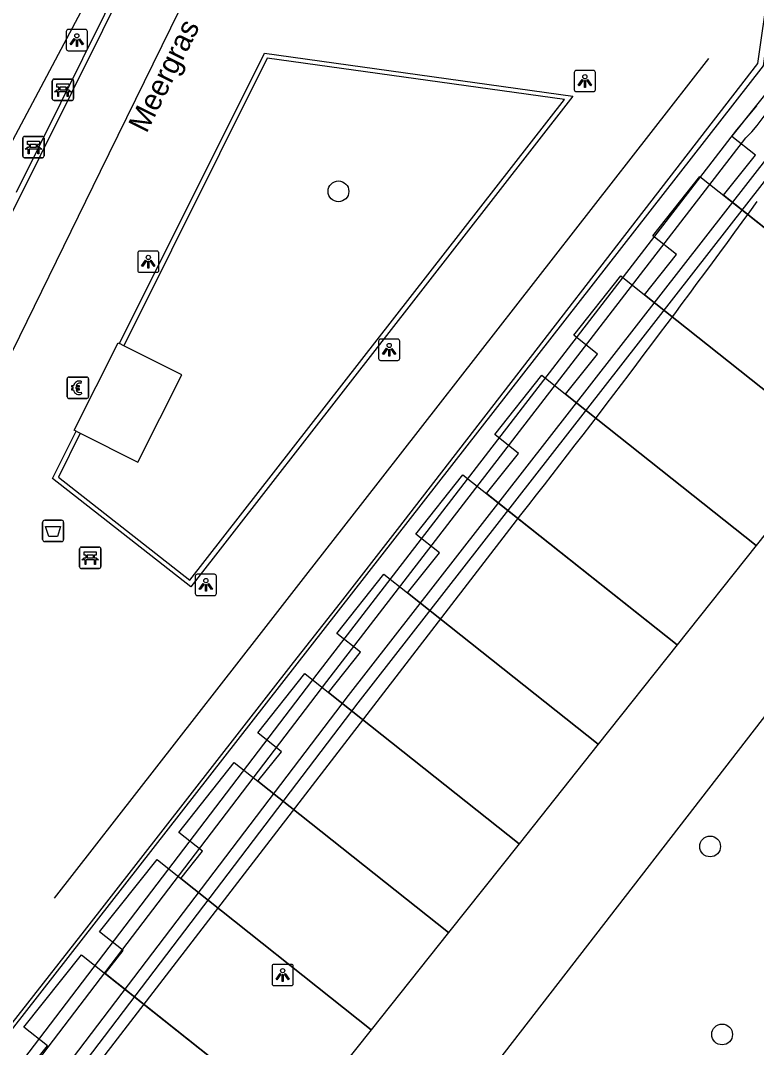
# Model space of a CAD drawing. Extents: x 155640 to 156810, y 382822 to 384046.
# Drawn here: x 156515.13 to 156549.69, y 383555.74 to 383603.99 of the extents above; entities that cross this region are included whole.
import ezdxf

# ---------------------------------------------------------------- set-up
doc = ezdxf.new("R2010")
doc.units = 0
for name, color, linetype in [('IMGEO_Afvalbak', 7, 'Continuous'), ('IMGEO_Bank', 7, 'Continuous'), ('IMGEO_Betaalautomaat', 7, 'Continuous'), ('IMGEO_Boom', 7, 'Continuous'), ('IMGEO_Groenvoorziening', 7, 'Continuous'), ('IMGEO_Lichtpunt', 7, 'Continuous'), ('IMGEO_Lijnafwatering', 7, 'Continuous'), ('IMGEO_Muur', 7, 'Continuous'), ('IMGEO_Openbare_ruimte_label', 7, 'Continuous'), ('IMGEO_Pand_vergunning_verleend', 7, 'Continuous'), ('IMGEO_Rijbaan_lokaal_gesloten', 7, 'Continuous'), ('IMGEO_Voetgangersgebied_gesloten', 7, 'Continuous'), ('IMGEO_Waterloop', 7, 'Continuous')]:
    doc.layers.add(name, color=color, linetype=linetype)

msp = doc.modelspace()

# ---------------------------------------------------------------- linework, layer by layer
at = {"layer": 'IMGEO_Afvalbak'}
for p, q in [((156516.16, 383579.606), (156516.16, 383580.406)), ((156516.16, 383580.406), (156516.16, 383579.606)), ((156516.26, 383580.506), (156517.05, 383580.506)), ((156517.05, 383580.506), (156516.26, 383580.506)), ((156517.15, 383580.406), (156517.15, 383579.606)), ((156517.15, 383579.606), (156517.15, 383580.406)), ((156517.05, 383579.506), (156516.26, 383579.506)), ((156516.26, 383579.506), (156517.05, 383579.506))]:
    msp.add_line(p, q, dxfattribs=at)
msp.add_lwpolyline([(156516.303, 383580.22), (156517.007, 383580.22), (156516.858, 383579.75), (156516.452, 383579.75), (156516.303, 383580.22)], dxfattribs=at)
for centre, start, end in [((156516.26, 383580.406), 90, 180), ((156516.26, 383580.406), 90, 180), ((156517.05, 383580.406), 0, 90), ((156517.05, 383580.406), 360, 90), ((156516.26, 383579.606), 180, 270), ((156516.26, 383579.606), 180, 270), ((156517.05, 383579.606), 270, 0), ((156517.05, 383579.606), 270, 0)]:
    msp.add_arc(centre, 0.1, start, end, dxfattribs=at)
at = {"layer": 'IMGEO_Bank'}
for p, q in [((156516.618, 383600.309), (156516.618, 383601.15)), ((156516.618, 383601.15), (156516.618, 383600.309)), ((156516.693, 383601.234), (156517.534, 383601.234)), ((156517.534, 383601.234), (156516.693, 383601.234)), ((156517.618, 383601.159), (156517.618, 383600.318)), ((156517.618, 383600.318), (156517.618, 383601.159)), ((156517.315, 383600.632), (156516.922, 383600.632)), ((156516.927, 383600.74), (156516.927, 383600.846)), ((156516.971, 383600.846), (156516.971, 383600.74)), ((156517.259, 383600.852), (156516.977, 383600.852)), ((156516.977, 383600.734), (156517.259, 383600.734)), ((156517.265, 383600.74), (156517.265, 383600.846)), ((156517.309, 383600.846), (156517.309, 383600.74)), ((156517.543, 383600.234), (156516.702, 383600.234)), ((156516.702, 383600.234), (156517.543, 383600.234)), ((156515.23, 383597.615), (156515.23, 383598.456)), ((156515.23, 383598.456), (156515.23, 383597.615)), ((156515.305, 383598.54), (156516.146, 383598.54)), ((156516.146, 383598.54), (156515.305, 383598.54)), ((156515.539, 383598.046), (156515.539, 383598.152)), ((156515.583, 383598.152), (156515.583, 383598.046)), ((156515.871, 383598.158), (156515.589, 383598.158)), ((156515.877, 383598.046), (156515.877, 383598.152)), ((156515.921, 383598.152), (156515.921, 383598.046)), ((156516.23, 383598.465), (156516.23, 383597.624)), ((156516.23, 383597.624), (156516.23, 383598.465)), ((156515.927, 383597.938), (156515.534, 383597.938)), ((156515.589, 383598.04), (156515.871, 383598.04)), ((156516.155, 383597.54), (156515.314, 383597.54)), ((156515.314, 383597.54), (156516.155, 383597.54)), ((156517.899, 383578.32), (156517.899, 383579.161)), ((156517.899, 383579.161), (156517.899, 383578.32)), ((156517.974, 383579.245), (156518.815, 383579.245)), ((156518.815, 383579.245), (156517.974, 383579.245)), ((156518.208, 383578.751), (156518.208, 383578.857)), ((156518.252, 383578.857), (156518.252, 383578.751)), ((156518.54, 383578.863), (156518.258, 383578.863)), ((156518.546, 383578.751), (156518.546, 383578.857)), ((156518.59, 383578.857), (156518.59, 383578.751)), ((156518.899, 383579.17), (156518.899, 383578.329)), ((156518.899, 383578.329), (156518.899, 383579.17)), ((156518.596, 383578.643), (156518.203, 383578.643)), ((156518.258, 383578.745), (156518.54, 383578.745)), ((156518.824, 383578.245), (156517.983, 383578.245)), ((156517.983, 383578.245), (156518.824, 383578.245))]:
    msp.add_line(p, q, dxfattribs=at)
for points in [[(156516.865, 383600.632), (156516.723, 383600.632), (156516.835, 383600.734), (156516.921, 383600.734)], [(156516.921, 383600.852), (156516.835, 383600.852), (156516.835, 383601.013), (156517.398, 383601.013), (156517.398, 383600.852), (156517.315, 383600.852)], [(156516.915, 383600.625), (156516.915, 383600.418), (156516.872, 383600.418), (156516.872, 383600.625)], [(156517.315, 383600.734), (156517.398, 383600.734), (156517.51, 383600.632), (156517.371, 383600.632)], [(156517.365, 383600.625), (156517.365, 383600.418), (156517.321, 383600.418), (156517.321, 383600.625)], [(156515.533, 383598.158), (156515.447, 383598.158), (156515.447, 383598.319), (156516.01, 383598.319), (156516.01, 383598.158), (156515.927, 383598.158)], [(156515.477, 383597.938), (156515.335, 383597.938), (156515.447, 383598.04), (156515.533, 383598.04)], [(156515.527, 383597.931), (156515.527, 383597.724), (156515.484, 383597.724), (156515.484, 383597.931)], [(156515.927, 383598.04), (156516.01, 383598.04), (156516.122, 383597.938), (156515.983, 383597.938)], [(156515.977, 383597.931), (156515.977, 383597.724), (156515.933, 383597.724), (156515.933, 383597.931)], [(156518.202, 383578.863), (156518.116, 383578.863), (156518.116, 383579.024), (156518.679, 383579.024), (156518.679, 383578.863), (156518.596, 383578.863)], [(156518.146, 383578.643), (156518.004, 383578.643), (156518.116, 383578.745), (156518.202, 383578.745)], [(156518.196, 383578.636), (156518.196, 383578.429), (156518.153, 383578.429), (156518.153, 383578.636)], [(156518.596, 383578.745), (156518.679, 383578.745), (156518.791, 383578.643), (156518.652, 383578.643)], [(156518.646, 383578.636), (156518.646, 383578.429), (156518.602, 383578.429), (156518.602, 383578.636)]]:
    msp.add_lwpolyline(points, dxfattribs=at)
for centre, radius, start, end in [((156516.696, 383601.156), 0.0779, 92.4484, 184.2845), ((156516.696, 383601.156), 0.0779, 92.4484, 184.2845), ((156517.54, 383601.156), 0.0779, 2.4484, 94.2845), ((156517.54, 383601.156), 0.0779, 2.4484, 94.2845), ((156516.865, 383600.625), 0.00671, 2.8957, 87.1043), ((156516.922, 383600.625), 0.00671, 92.8957, 177.1043), ((156516.92, 383600.845), 0.00671, 2.8957, 87.1043), ((156516.92, 383600.741), 0.00671, 272.8957, 357.1043), ((156516.977, 383600.845), 0.00671, 92.8957, 177.1043), ((156516.977, 383600.741), 0.00671, 182.8957, 267.1043), ((156517.259, 383600.845), 0.00671, 2.8957, 87.1043), ((156517.259, 383600.741), 0.00671, 272.8957, 357.1043), ((156517.316, 383600.845), 0.00671, 92.8957, 177.1043), ((156517.316, 383600.741), 0.00671, 182.8957, 267.1043), ((156517.314, 383600.625), 0.00671, 2.8957, 87.1043), ((156517.371, 383600.625), 0.00671, 92.8957, 177.1043), ((156516.696, 383600.312), 0.0779, 182.4484, 274.2845), ((156516.696, 383600.312), 0.0779, 182.4484, 274.2845), ((156517.54, 383600.312), 0.0779, 272.4484, 4.2845), ((156517.54, 383600.312), 0.0779, 272.4484, 4.2845), ((156515.308, 383598.462), 0.0779, 92.4484, 184.2845), ((156515.308, 383598.462), 0.0779, 92.4484, 184.2845), ((156515.532, 383598.151), 0.00671, 2.8957, 87.1043), ((156515.589, 383598.151), 0.00671, 92.8957, 177.1043), ((156515.871, 383598.151), 0.00671, 2.8957, 87.1043), ((156515.928, 383598.151), 0.00671, 92.8957, 177.1043), ((156516.152, 383598.462), 0.0779, 2.4484, 94.2845), ((156516.152, 383598.462), 0.0779, 2.4484, 94.2845), ((156515.477, 383597.931), 0.00671, 2.8957, 87.1043), ((156515.534, 383597.931), 0.00671, 92.8957, 177.1043), ((156515.532, 383598.047), 0.00671, 272.8957, 357.1043), ((156515.589, 383598.047), 0.00671, 182.8957, 267.1043), ((156515.871, 383598.047), 0.00671, 272.8957, 357.1043), ((156515.928, 383598.047), 0.00671, 182.8957, 267.1043), ((156515.926, 383597.931), 0.00671, 2.8957, 87.1043), ((156515.983, 383597.931), 0.00671, 92.8957, 177.1043), ((156515.308, 383597.618), 0.0779, 182.4484, 274.2845), ((156515.308, 383597.618), 0.0779, 182.4484, 274.2845), ((156516.152, 383597.618), 0.0779, 272.4484, 4.2845), ((156516.152, 383597.618), 0.0779, 272.4484, 4.2845), ((156517.977, 383579.167), 0.0779, 92.4484, 184.2845), ((156517.977, 383579.167), 0.0779, 92.4484, 184.2845), ((156518.201, 383578.856), 0.00671, 2.8957, 87.1043), ((156518.258, 383578.856), 0.00671, 92.8957, 177.1043), ((156518.54, 383578.856), 0.00671, 2.8957, 87.1043), ((156518.597, 383578.856), 0.00671, 92.8957, 177.1043), ((156518.821, 383579.167), 0.0779, 2.4484, 94.2845), ((156518.821, 383579.167), 0.0779, 2.4484, 94.2845), ((156518.146, 383578.636), 0.00671, 2.8957, 87.1043), ((156518.203, 383578.636), 0.00671, 92.8957, 177.1043), ((156518.201, 383578.752), 0.00671, 272.8957, 357.1043), ((156518.258, 383578.752), 0.00671, 182.8957, 267.1043), ((156518.54, 383578.752), 0.00671, 272.8957, 357.1043), ((156518.597, 383578.752), 0.00671, 182.8957, 267.1043), ((156518.595, 383578.636), 0.00671, 2.8957, 87.1043), ((156518.652, 383578.636), 0.00671, 92.8957, 177.1043), ((156517.977, 383578.323), 0.0779, 182.4484, 274.2845), ((156517.977, 383578.323), 0.0779, 182.4484, 274.2845), ((156518.821, 383578.323), 0.0779, 272.4484, 4.2845), ((156518.821, 383578.323), 0.0779, 272.4484, 4.2845)]:
    msp.add_arc(centre, radius, start, end, dxfattribs=at)
at = {"layer": 'IMGEO_Betaalautomaat'}
for p, q in [((156517.317, 383586.307), (156517.317, 383587.148)), ((156517.317, 383587.148), (156517.317, 383586.307)), ((156517.392, 383587.231), (156518.233, 383587.231)), ((156518.233, 383587.231), (156517.392, 383587.231)), ((156517.979, 383587.036), (156517.962, 383586.936)), ((156518.316, 383587.157), (156518.316, 383586.316)), ((156518.316, 383586.316), (156518.316, 383587.157)), ((156517.6, 383586.695), (156517.6, 383586.763)), ((156517.721, 383586.763), (156517.721, 383586.695)), ((156518.242, 383586.232), (156517.401, 383586.232)), ((156517.401, 383586.232), (156518.242, 383586.232)), ((156517.966, 383586.53), (156517.988, 383586.443))]:
    msp.add_line(p, q, dxfattribs=at)
for points in [[(156517.6, 383586.763), (156517.531, 383586.763), (156517.531, 383586.832), (156517.61, 383586.832)], [(156517.605, 383586.626), (156517.531, 383586.626), (156517.531, 383586.695), (156517.6, 383586.695)], [(156517.732, 383586.832), (156517.879, 383586.832), (156517.879, 383586.763), (156517.721, 383586.763)], [(156517.721, 383586.695), (156517.879, 383586.695), (156517.879, 383586.626), (156517.735, 383586.626)]]:
    msp.add_lwpolyline(points, dxfattribs=at)
for centre, radius, start, end in [((156517.395, 383587.154), 0.0779, 92.4484, 184.2845), ((156517.395, 383587.154), 0.0779, 92.4484, 184.2845), ((156517.893, 383586.756), 0.293, 73.014, 165.0139), ((156518.239, 383587.154), 0.0779, 2.4484, 94.2845), ((156518.239, 383587.154), 0.0779, 2.4484, 94.2845), ((156517.866, 383586.681), 0.267, 191.8096, 297.0389), ((156517.899, 383586.769), 0.179, 69.3236, 159.5683), ((156517.899, 383586.696), 0.179, 202.7625, 291.8693), ((156517.395, 383586.31), 0.0779, 182.4484, 274.2845), ((156517.395, 383586.31), 0.0779, 182.4484, 274.2845), ((156518.239, 383586.31), 0.0779, 272.4484, 4.2845), ((156518.239, 383586.31), 0.0779, 272.4484, 4.2845)]:
    msp.add_arc(centre, radius, start, end, dxfattribs=at)
at = {"layer": 'IMGEO_Boom'}
for centre in [(156530.057, 383595.961), (156547.515, 383565.182), (156548.078, 383556.351)]:
    msp.add_circle(centre, 0.489, dxfattribs=at)
at = {"layer": 'IMGEO_Groenvoorziening'}
for points in [[(156495.718, 383529.538), (156529.05, 383573.281), (156548.765, 383598.855), (156549.707, 383599.986)], [(156552.006, 383598.975), (156550.77, 383597.349), (156530.966, 383571.925), (156497.589, 383528.035)], [(156503.692, 383535.399), (156538.265, 383580.296)], [(156556.661, 383579.807), (156509.15, 383518.42)]]:
    msp.add_lwpolyline(points, dxfattribs=at)
msp.add_arc((156125.933, 383903.541), 523.932, 321.90554, 323.98601, dxfattribs=at)
at = {"layer": 'IMGEO_Lichtpunt'}
for p, q in [((156517.27, 383603.472), (156517.27, 383602.665)), ((156517.27, 383603.472), (156517.27, 383602.665)), ((156518.172, 383603.567), (156517.364, 383603.567)), ((156518.172, 383603.567), (156517.364, 383603.567)), ((156518.266, 383602.665), (156518.266, 383603.472)), ((156518.266, 383602.665), (156518.266, 383603.472)), ((156517.364, 383602.571), (156518.172, 383602.571)), ((156517.364, 383602.571), (156518.172, 383602.571)), ((156541.132, 383601.547), (156541.132, 383600.74)), ((156541.132, 383601.547), (156541.132, 383600.74)), ((156542.034, 383601.642), (156541.226, 383601.642)), ((156542.034, 383601.642), (156541.226, 383601.642)), ((156542.128, 383600.74), (156542.128, 383601.547)), ((156542.128, 383600.74), (156542.128, 383601.547)), ((156541.226, 383600.646), (156542.034, 383600.646)), ((156541.226, 383600.646), (156542.034, 383600.646)), ((156520.627, 383593.059), (156520.627, 383592.252)), ((156520.627, 383593.059), (156520.627, 383592.252)), ((156521.529, 383593.154), (156520.721, 383593.154)), ((156521.529, 383593.154), (156520.721, 383593.154)), ((156521.623, 383592.252), (156521.623, 383593.059)), ((156521.623, 383592.252), (156521.623, 383593.059)), ((156520.721, 383592.158), (156521.529, 383592.158)), ((156520.721, 383592.158), (156521.529, 383592.158)), ((156532.843, 383589.017), (156532.035, 383589.017)), ((156532.843, 383589.017), (156532.035, 383589.017)), ((156531.941, 383588.922), (156531.941, 383588.115)), ((156531.941, 383588.922), (156531.941, 383588.115)), ((156532.937, 383588.115), (156532.937, 383588.922)), ((156532.937, 383588.115), (156532.937, 383588.922)), ((156532.035, 383588.021), (156532.843, 383588.021)), ((156532.035, 383588.021), (156532.843, 383588.021)), ((156523.33, 383577.875), (156523.33, 383577.068)), ((156523.33, 383577.875), (156523.33, 383577.068)), ((156524.232, 383577.97), (156523.424, 383577.97)), ((156524.232, 383577.97), (156523.424, 383577.97)), ((156524.326, 383577.068), (156524.326, 383577.875)), ((156524.326, 383577.068), (156524.326, 383577.875)), ((156523.424, 383576.974), (156524.232, 383576.974)), ((156523.424, 383576.974), (156524.232, 383576.974)), ((156526.938, 383559.548), (156526.938, 383558.741)), ((156526.938, 383559.548), (156526.938, 383558.741)), ((156527.84, 383559.643), (156527.032, 383559.643)), ((156527.84, 383559.643), (156527.032, 383559.643)), ((156527.934, 383558.741), (156527.934, 383559.548)), ((156527.934, 383558.741), (156527.934, 383559.548)), ((156527.032, 383558.647), (156527.84, 383558.647)), ((156527.032, 383558.647), (156527.84, 383558.647))]:
    msp.add_line(p, q, dxfattribs=at)
for points in [[(156517.644, 383603.136), (156517.683, 383603.108), (156517.495, 383602.846), (156517.457, 383602.873), (156517.644, 383603.136)], [(156517.746, 383603.088), (156517.793, 383603.088), (156517.793, 383602.766), (156517.746, 383602.766), (156517.746, 383603.088)], [(156517.856, 383603.108), (156517.894, 383603.135), (156518.081, 383602.873), (156518.042, 383602.845), (156517.856, 383603.108)], [(156541.506, 383601.211), (156541.545, 383601.183), (156541.357, 383600.921), (156541.319, 383600.948), (156541.506, 383601.211)], [(156541.608, 383601.163), (156541.655, 383601.163), (156541.655, 383600.841), (156541.608, 383600.841), (156541.608, 383601.163)], [(156541.718, 383601.183), (156541.756, 383601.21), (156541.943, 383600.948), (156541.904, 383600.92), (156541.718, 383601.183)], [(156521.001, 383592.723), (156521.04, 383592.695), (156520.852, 383592.433), (156520.814, 383592.46), (156521.001, 383592.723)], [(156521.103, 383592.675), (156521.15, 383592.675), (156521.15, 383592.353), (156521.103, 383592.353), (156521.103, 383592.675)], [(156521.213, 383592.695), (156521.251, 383592.722), (156521.438, 383592.46), (156521.399, 383592.432), (156521.213, 383592.695)], [(156532.315, 383588.586), (156532.354, 383588.558), (156532.166, 383588.296), (156532.128, 383588.323), (156532.315, 383588.586)], [(156532.417, 383588.538), (156532.464, 383588.538), (156532.464, 383588.216), (156532.417, 383588.216), (156532.417, 383588.538)], [(156532.527, 383588.558), (156532.565, 383588.585), (156532.752, 383588.323), (156532.713, 383588.295), (156532.527, 383588.558)], [(156523.704, 383577.539), (156523.743, 383577.511), (156523.555, 383577.249), (156523.517, 383577.276), (156523.704, 383577.539)], [(156523.806, 383577.491), (156523.853, 383577.491), (156523.853, 383577.169), (156523.806, 383577.169), (156523.806, 383577.491)], [(156523.916, 383577.511), (156523.954, 383577.538), (156524.141, 383577.276), (156524.102, 383577.248), (156523.916, 383577.511)], [(156527.312, 383559.212), (156527.351, 383559.184), (156527.163, 383558.922), (156527.125, 383558.949), (156527.312, 383559.212)], [(156527.414, 383559.164), (156527.461, 383559.164), (156527.461, 383558.842), (156527.414, 383558.842), (156527.414, 383559.164)], [(156527.524, 383559.184), (156527.562, 383559.211), (156527.749, 383558.949), (156527.71, 383558.921), (156527.524, 383559.184)]]:
    msp.add_lwpolyline(points, dxfattribs=at)
for centre in [(156517.769, 383603.27), (156541.631, 383601.345), (156521.126, 383592.857), (156532.44, 383588.72), (156523.829, 383577.673), (156527.437, 383559.346)]:
    msp.add_circle(centre, 0.0994, dxfattribs=at)
for centre, start, end in [((156517.364, 383603.472), 90, 180), ((156517.364, 383603.472), 90, 180), ((156518.172, 383603.472), 0, 90), ((156518.172, 383603.472), 0, 90), ((156517.364, 383602.665), 180, 270), ((156517.364, 383602.665), 180, 270), ((156518.172, 383602.665), 270, 0), ((156518.172, 383602.665), 270, 360), ((156541.226, 383601.547), 90, 180), ((156541.226, 383601.547), 90, 180), ((156542.034, 383601.547), 0, 90), ((156542.034, 383601.547), 0, 90), ((156541.226, 383600.74), 180, 270), ((156541.226, 383600.74), 180, 270), ((156542.034, 383600.74), 270, 0), ((156542.034, 383600.74), 270, 360), ((156520.721, 383593.059), 90, 180), ((156520.721, 383593.059), 90, 180), ((156521.529, 383593.059), 0, 90), ((156521.529, 383593.059), 0, 90), ((156520.721, 383592.252), 180, 270), ((156520.721, 383592.252), 180, 270), ((156521.529, 383592.252), 270, 0), ((156521.529, 383592.252), 270, 360), ((156532.035, 383588.922), 90, 180), ((156532.035, 383588.922), 90, 180), ((156532.843, 383588.922), 0, 90), ((156532.843, 383588.922), 0, 90), ((156532.035, 383588.115), 180, 270), ((156532.035, 383588.115), 180, 270), ((156532.843, 383588.115), 270, 0), ((156532.843, 383588.115), 270, 360), ((156523.424, 383577.875), 90, 180), ((156523.424, 383577.875), 90, 180), ((156524.232, 383577.875), 0, 90), ((156524.232, 383577.875), 0, 90), ((156523.424, 383577.068), 180, 270), ((156523.424, 383577.068), 180, 270), ((156524.232, 383577.068), 270, 0), ((156524.232, 383577.068), 270, 360), ((156527.032, 383559.548), 90, 180), ((156527.032, 383559.548), 90, 180), ((156527.84, 383559.548), 0, 90), ((156527.84, 383559.548), 0, 90), ((156527.032, 383558.741), 180, 270), ((156527.032, 383558.741), 180, 270), ((156527.84, 383558.741), 270, 0), ((156527.84, 383558.741), 270, 360)]:
    msp.add_arc(centre, 0.0946, start, end, dxfattribs=at)
at = {"layer": 'IMGEO_Lijnafwatering'}
for points in [[(156518.88, 383596.903), (156527.152, 383613.781)], [(156547.431, 383602.197), (156531.188, 383581.349)], [(156510.608, 383580.026), (156518.88, 383596.903)], [(156531.188, 383581.349), (156528.51, 383577.911), (156526.313, 383575.091), (156516.703, 383562.756)]]:
    msp.add_lwpolyline(points, dxfattribs=at)
at = {"layer": 'IMGEO_Muur'}
for points in [[(156533.646, 383633.045), (156507.234, 383579.938), (156469.136, 383609.655), (156454.553, 383640.906)], [(156489.038, 383523.547), (156488.884, 383523.896), (156518.136, 383561.224), (156527.939, 383573.822), (156530.147, 383576.636), (156532.824, 383580.075), (156549.757, 383601.973), (156553.649, 383629.149)], [(156553.649, 383629.149), (156553.807, 383629.123), (156550.011, 383601.865), (156504.027, 383542.902), (156491.113, 383526.227)], [(156514.94, 383595.917), (156526.36, 383618.972)], [(156519.77, 383588.81), (156526.579, 383602.451), (156541.074, 383600.43), (156523.125, 383577.388), (156516.632, 383582.478), (156517.731, 383584.691)], [(156517.924, 383584.594), (156516.913, 383582.532), (156523.081, 383577.698), (156540.668, 383600.271), (156526.704, 383602.215), (156519.978, 383588.705)], [(156519.978, 383588.705), (156519.775, 383588.807), (156519.77, 383588.81)], [(156517.731, 383584.691), (156517.924, 383584.594)]]:
    msp.add_lwpolyline(points, dxfattribs=at)
at = {"layer": 'IMGEO_Pand_vergunning_verleend'}
for points in [[(156533.045, 383632.833), (156494.418, 383560.103), (156449.18, 383594.892), (156450.711, 383595.595), (156449.358, 383598.538), (156447.864, 383597.851), (156446.042, 383601.815), (156447.521, 383602.495), (156446.189, 383605.394), (156444.717, 383604.718), (156442.926, 383608.616), (156444.388, 383609.288), (156443.057, 383612.183), (156441.68, 383611.55), (156439.86, 383615.509), (156441.301, 383616.171), (156439.969, 383619.07), (156438.531, 383618.409), (156437.029, 383621.678)], [(156557.099, 383588.667), (156548.15, 383595.777), (156549.646, 383597.661), (156548.535, 383598.543), (156550.75, 383601.332)], [(156544.438, 383591.106), (156545.934, 383592.989), (156544.823, 383593.872), (156547.038, 383596.66), (156557.099, 383588.667)], [(156540.726, 383586.435), (156542.223, 383588.318), (156541.111, 383589.201), (156543.327, 383591.989), (156544.438, 383591.106)], [(156544.438, 383591.106), (156553.387, 383583.995)], [(156553.387, 383583.995), (156544.438, 383591.106), (156544.438, 383591.106)], [(156545.964, 383574.653), (156537.015, 383581.763), (156538.511, 383583.647), (156537.4, 383584.53), (156539.615, 383587.318), (156540.726, 383586.435)], [(156540.726, 383586.435), (156549.675, 383579.324)], [(156549.675, 383579.324), (156540.726, 383586.435), (156540.726, 383586.435)], [(156553.387, 383583.995), (156549.675, 383579.324)], [(156533.303, 383577.092), (156534.799, 383578.975), (156533.688, 383579.858), (156535.903, 383582.646), (156545.964, 383574.653)], [(156549.675, 383579.324), (156545.964, 383574.653)], [(156529.591, 383572.421), (156531.088, 383574.304), (156529.976, 383575.187), (156532.192, 383577.975), (156533.303, 383577.092)], [(156542.252, 383569.981), (156533.303, 383577.092), (156533.303, 383577.092)], [(156533.303, 383577.092), (156542.252, 383569.981)], [(156545.964, 383574.653), (156542.252, 383569.981)], [(156526.277, 383568.25), (156527.376, 383569.633), (156526.265, 383570.516), (156528.48, 383573.304), (156529.591, 383572.421)], [(156529.591, 383572.421), (156538.54, 383565.31)], [(156538.54, 383565.31), (156529.591, 383572.421), (156529.591, 383572.421)], [(156542.252, 383569.981), (156538.54, 383565.31)], [(156522.649, 383563.683), (156523.664, 383564.961), (156522.553, 383565.844), (156525.166, 383569.133), (156526.277, 383568.25)], [(156526.277, 383568.25), (156535.227, 383561.14)], [(156535.227, 383561.14), (156526.277, 383568.25), (156526.277, 383568.25)], [(156538.54, 383565.31), (156535.227, 383561.14)], [(156528.042, 383552.097), (156519.093, 383559.208), (156519.953, 383560.29), (156518.841, 383561.173), (156521.538, 383564.566), (156522.649, 383563.683)], [(156522.649, 383563.683), (156531.598, 383556.573)], [(156531.598, 383556.573), (156522.649, 383563.683), (156522.649, 383563.683)], [(156535.227, 383561.14), (156531.598, 383556.573)], [(156515.536, 383554.732), (156516.396, 383555.814), (156515.285, 383556.697), (156517.981, 383560.09), (156528.042, 383552.097)], [(156531.598, 383556.573), (156528.042, 383552.097)]]:
    msp.add_lwpolyline(points, dxfattribs=at)
at = {"layer": 'IMGEO_Rijbaan_lokaal_gesloten'}
msp.add_lwpolyline([(156517.924, 383584.594), (156520.634, 383583.23), (156522.7, 383587.335), (156519.978, 383588.705)], dxfattribs=at)
at = {"layer": 'IMGEO_Voetgangersgebied_gesloten'}
msp.add_lwpolyline([(156517.731, 383584.691), (156517.642, 383584.736), (156519.708, 383588.841), (156519.77, 383588.81)], dxfattribs=at)
at = {"layer": 'IMGEO_Waterloop'}
for points in [[(156496.396, 383529.49), (156529.504, 383572.933), (156549.196, 383598.478)], [(156550.334, 383597.719), (156530.513, 383572.274), (156497.423, 383528.748)]]:
    msp.add_lwpolyline(points, dxfattribs=at)
msp.add_arc((156542.834, 383604.754), 8.937, 315.3894, 355.3954, dxfattribs=at)

# ---------------------------------------------------------------- texts
at = {"layer": 'IMGEO_Openbare_ruimte_label'}
msp.add_text('Meergras', height=1, rotation=63.5374, dxfattribs=at).set_placement((156521.043, 383598.655))

doc.saveas('drawing.dxf')
